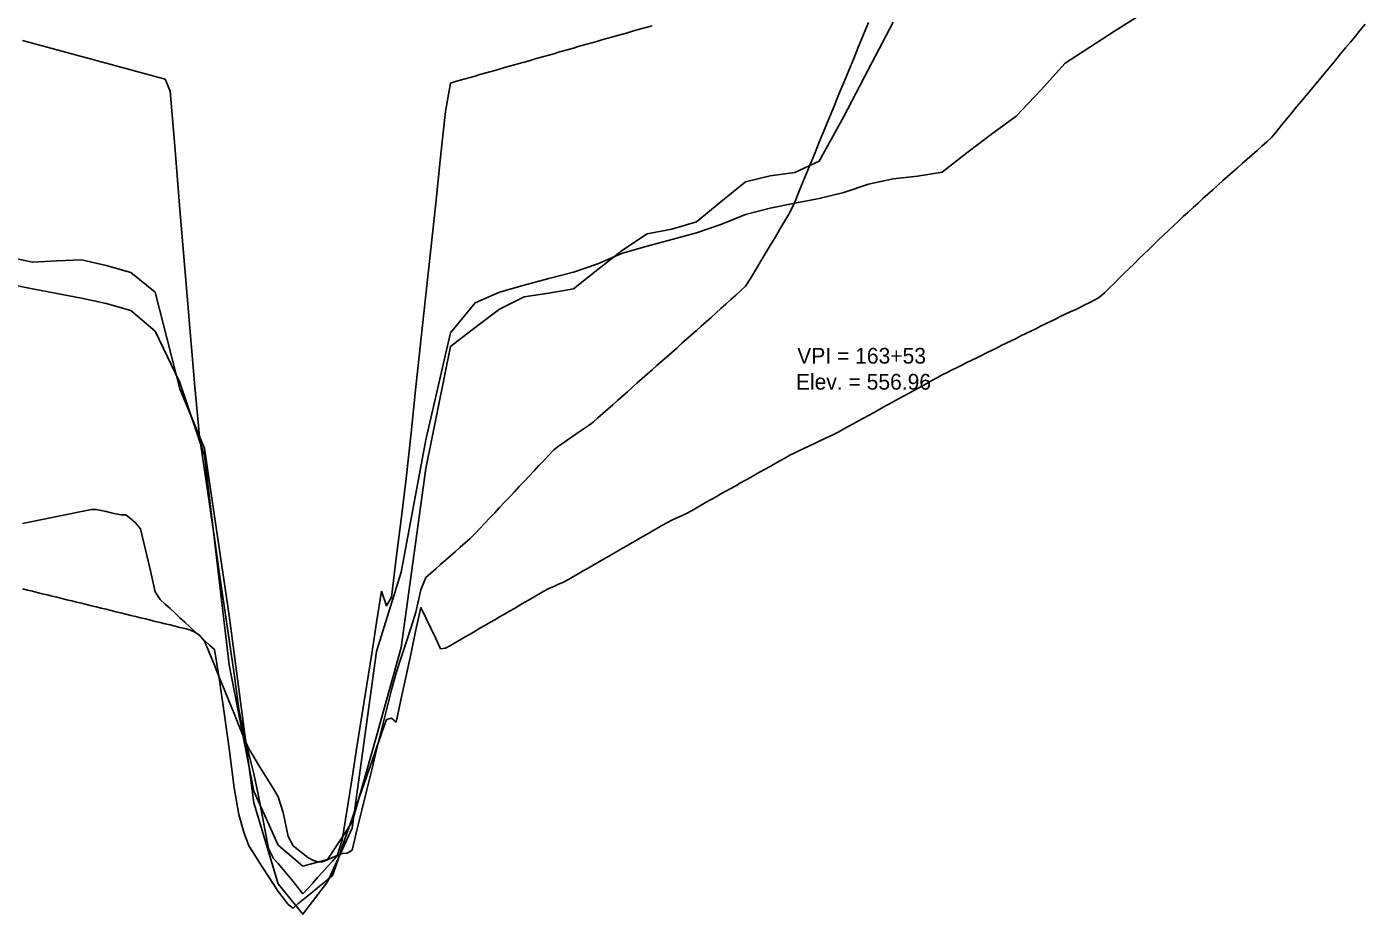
# Model space of a CAD drawing. Extents: x 1733571 to 1737171, y 1214895 to 1219895.
# Drawn here: x 1735360.8 to 1735633, y 1217773.2 to 1217953.6 of the extents above; entities that cross this region are included whole.
import ezdxf

# ---------------------------------------------------------------- set-up
doc = ezdxf.new("R2010")
doc.units = 0
for name, color, linetype in [('RD_DDB_Profile_EX', 7, 'Continuous'), ('RD_DDB_Profile_Lbl', 7, 'Continuous'), ('RD_Sketch1', 7, 'Continuous'), ('RD_Sketch2', 7, 'Continuous'), ('RD_Sketch3', 7, 'Continuous'), ('RD_Sketch4', 7, 'Continuous')]:
    doc.layers.add(name, color=color, linetype=linetype)

msp = doc.modelspace()

# ---------------------------------------------------------------- linework, layer by layer
at = {"layer": 'RD_DDB_Profile_EX'}
for points in [[(1735403.9887, 1217814.82595), (1735404.9887, 1217809.77976), (1735405.9887, 1217805.75508), (1735406.9887, 1217801.7304), (1735407.9887, 1217797.21719), (1735408.9887, 1217791.86495), (1735409.9887, 1217786.51271), (1735410.9887, 1217784.49053), (1735411.9887, 1217783.49618), (1735412.9887, 1217782.28653), (1735413.9887, 1217781.04718), (1735414.9887, 1217779.80783), (1735415.9887, 1217778.56847), (1735416.9887, 1217777.32912), (1735417.9887, 1217778.37844), (1735418.9887, 1217779.49479), (1735419.9887, 1217780.61114), (1735420.9887, 1217781.72749), (1735421.9887, 1217782.84384), (1735422.9887, 1217783.96019), (1735423.9887, 1217785.04162), (1735424.9887, 1217788.22009), (1735425.9887, 1217794.54679), (1735426.9887, 1217800.87348), (1735427.9887, 1217807.20017), (1735428.9887, 1217813.52686), (1735429.9887, 1217819.85355), (1735430.9887, 1217826.18025), (1735431.9887, 1217832.50694), (1735432.9887, 1217838.83898), (1735433.9887, 1217835.85161), (1735434.9887, 1217837.60997), (1735435.9887, 1217845.53436), (1735436.9887, 1217853.45875), (1735437.9887, 1217861.74643), (1735438.9887, 1217871.07993), (1735439.9887, 1217880.41343), (1735440.9887, 1217889.74693), (1735441.9887, 1217899.08043), (1735442.9887, 1217908.41393), (1735443.9887, 1217917.74743), (1735444.9887, 1217927.08094), (1735445.9887, 1217936.41444), (1735446.9887, 1217942.17422), (1735447.9887, 1217942.45977), (1735448.9887, 1217942.74531), (1735449.9887, 1217943.03086), (1735450.9887, 1217943.31641), (1735451.9887, 1217943.60195), (1735452.9887, 1217943.8868), (1735453.9887, 1217944.17071), (1735454.9887, 1217944.45463), (1735455.9887, 1217944.73854), (1735456.9887, 1217945.02246), (1735457.9887, 1217945.30637), (1735458.9887, 1217945.59029), (1735459.9887, 1217945.8742), (1735460.9887, 1217946.15812), (1735461.9887, 1217946.44203), (1735462.9887, 1217946.72595), (1735463.9887, 1217947.00986), (1735464.9887, 1217947.29378), (1735465.9887, 1217947.57769), (1735466.9887, 1217947.86161), (1735467.9887, 1217948.14552), (1735468.9887, 1217948.42944), (1735469.9887, 1217948.71335), (1735470.9887, 1217948.99727), (1735471.9887, 1217949.28817), (1735472.9887, 1217949.57685), (1735473.9887, 1217949.86134), (1735474.9887, 1217950.14583), (1735475.9887, 1217950.43032), (1735476.9887, 1217950.71481), (1735477.9887, 1217950.9993), (1735478.9887, 1217951.28379), (1735479.9887, 1217951.56828), (1735480.9887, 1217951.85278), (1735481.9887, 1217952.13727), (1735482.9887, 1217952.42176), (1735483.9887, 1217952.70625), (1735484.9887, 1217952.99074), (1735485.9887, 1217953.27523), (1735486.9887, 1217953.55972), (1735487.9887, 1217953.84421)], [(1735359.9887, 1217950.80532), (1735360.9887, 1217950.53363), (1735361.9887, 1217950.26194), (1735362.9887, 1217949.99025), (1735363.9887, 1217949.71856), (1735364.9887, 1217949.44687), (1735365.9887, 1217949.17518), (1735366.9887, 1217948.90787), (1735367.9887, 1217948.63642), (1735368.9887, 1217948.36496), (1735369.9887, 1217948.0935), (1735370.9887, 1217947.82205), (1735371.9887, 1217947.55059), (1735372.9887, 1217947.27913), (1735373.9887, 1217947.00768), (1735374.9887, 1217946.73622), (1735375.9887, 1217946.46476), (1735376.9887, 1217946.19331), (1735377.9887, 1217945.92185), (1735378.9887, 1217945.65039), (1735379.9887, 1217945.37894), (1735380.9887, 1217945.10748), (1735381.9887, 1217944.83603), (1735382.9887, 1217944.56457), (1735383.9887, 1217944.29311), (1735384.9887, 1217944.02166), (1735385.9887, 1217943.7502), (1735386.9887, 1217943.47874), (1735387.9887, 1217943.20729), (1735388.9887, 1217942.93583), (1735389.9887, 1217940.52821), (1735390.9887, 1217928.49516), (1735391.9887, 1217916.46924), (1735392.9887, 1217904.44768), (1735393.9887, 1217892.42613), (1735394.9887, 1217880.40457), (1735395.9887, 1217870.33538), (1735396.9887, 1217863.44004), (1735397.9887, 1217856.5447), (1735398.9887, 1217849.64936), (1735399.9887, 1217842.75402), (1735400.9887, 1217835.85868), (1735401.9887, 1217828.96334), (1735402.9887, 1217822.068), (1735403.9887, 1217814.82595)]]:
    msp.add_lwpolyline(points, dxfattribs=at)
at = {"layer": 'RD_Sketch1'}
for points in [[(1735505.9887, 1217899.95274), (1735506.9887, 1217900.85824), (1735507.9887, 1217902.43645), (1735508.9887, 1217904.10918), (1735509.9887, 1217905.78213), (1735510.9887, 1217907.45531), (1735511.9887, 1217909.12871), (1735512.9887, 1217910.80233), (1735513.9887, 1217912.47617), (1735514.9887, 1217914.15024), (1735515.9887, 1217915.82453), (1735516.9887, 1217917.95232), (1735517.9887, 1217920.39026), (1735518.9887, 1217922.82795), (1735519.9887, 1217925.26538), (1735520.9887, 1217927.70255), (1735521.9887, 1217930.13946), (1735522.9887, 1217932.57611), (1735523.9887, 1217935.0125), (1735524.9887, 1217937.44862), (1735525.9887, 1217939.88448), (1735526.9887, 1217942.32008), (1735527.9887, 1217944.75541), (1735528.9887, 1217947.19048), (1735529.9887, 1217949.62528), (1735530.9887, 1217952.05982), (1735531.9887, 1217954.49408)], [(1735405.9887, 1217806.7852), (1735406.9887, 1217805.16123), (1735407.9887, 1217803.53725), (1735408.9887, 1217801.91328), (1735409.9887, 1217800.28931), (1735410.9887, 1217798.66534), (1735411.9887, 1217797.04137), (1735412.9887, 1217793.84536), (1735413.9887, 1217788.94765), (1735414.9887, 1217787.08806), (1735415.9887, 1217786.2937), (1735416.9887, 1217785.49933), (1735417.9887, 1217784.70497), (1735418.9887, 1217784.13339), (1735419.9887, 1217783.84017), (1735420.9887, 1217783.79345), (1735421.9887, 1217784.22864), (1735422.9887, 1217784.66384), (1735423.9887, 1217785.09904), (1735424.9887, 1217785.53424), (1735425.9887, 1217785.57916), (1735426.9887, 1217786.21749), (1735427.9887, 1217790.28585), (1735428.9887, 1217794.35422), (1735429.9887, 1217798.42258), (1735430.9887, 1217802.49095), (1735431.9887, 1217806.55932), (1735432.9887, 1217810.62768), (1735433.9887, 1217814.69605), (1735434.9887, 1217818.76442), (1735435.9887, 1217822.27353), (1735436.9887, 1217825.35337), (1735437.9887, 1217828.43321), (1735438.9887, 1217831.51305), (1735439.9887, 1217834.6022), (1735440.9887, 1217839.15742), (1735441.9887, 1217841.66362), (1735442.9887, 1217842.54373), (1735443.9887, 1217843.42385), (1735444.9887, 1217844.30396), (1735445.9887, 1217845.18408), (1735446.9887, 1217846.06419), (1735447.9887, 1217846.94431), (1735448.9887, 1217847.82443), (1735449.9887, 1217848.70454), (1735450.9887, 1217849.58466), (1735451.9887, 1217850.55494), (1735452.9887, 1217851.61814), (1735453.9887, 1217852.68134), (1735454.9887, 1217853.74454), (1735455.9887, 1217854.80774), (1735456.9887, 1217855.87094), (1735457.9887, 1217856.93415), (1735458.9887, 1217857.99735), (1735459.9887, 1217859.06055), (1735460.9887, 1217860.12375), (1735461.9887, 1217861.18695), (1735462.9887, 1217862.25015), (1735463.9887, 1217863.31335), (1735464.9887, 1217864.37655), (1735465.9887, 1217865.43976), (1735466.9887, 1217866.50296), (1735467.9887, 1217867.56616), (1735468.9887, 1217868.35172), (1735469.9887, 1217869.04359), (1735470.9887, 1217869.73546), (1735471.9887, 1217870.42733), (1735472.9887, 1217871.1192), (1735473.9887, 1217871.81107), (1735474.9887, 1217872.50294), (1735475.9887, 1217873.20844), (1735476.9887, 1217874.09588), (1735477.9887, 1217874.98332), (1735478.9887, 1217875.87077), (1735479.9887, 1217876.75821), (1735480.9887, 1217877.64566), (1735481.9887, 1217878.5331), (1735482.9887, 1217879.42055), (1735483.9887, 1217880.30799), (1735484.9887, 1217881.19543), (1735485.9887, 1217882.08288), (1735486.9887, 1217882.97032), (1735487.9887, 1217883.85777), (1735488.9887, 1217884.74521), (1735489.9887, 1217885.63266), (1735490.9887, 1217886.5201), (1735491.9887, 1217887.40754), (1735492.9887, 1217888.29499), (1735493.9887, 1217889.18243), (1735494.9887, 1217890.06988), (1735495.9887, 1217890.95732), (1735496.9887, 1217891.84477), (1735497.9887, 1217892.73221), (1735498.9887, 1217893.62677), (1735499.9887, 1217894.52914), (1735500.9887, 1217895.43196), (1735501.9887, 1217896.33523), (1735502.9887, 1217897.23894), (1735503.9887, 1217898.14309), (1735504.9887, 1217899.0477), (1735505.9887, 1217899.95274)], [(1735359.9887, 1217839.32341), (1735360.9887, 1217839.07863), (1735361.9887, 1217838.83385), (1735362.9887, 1217838.58908), (1735363.9887, 1217838.3443), (1735364.9887, 1217838.09952), (1735365.9887, 1217837.85474), (1735366.9887, 1217837.60996), (1735367.9887, 1217837.36518), (1735368.9887, 1217837.1204), (1735369.9887, 1217836.87562), (1735370.9887, 1217836.63084), (1735371.9887, 1217836.38607), (1735372.9887, 1217836.14129), (1735373.9887, 1217835.89651), (1735374.9887, 1217835.65173), (1735375.9887, 1217835.40695), (1735376.9887, 1217835.16217), (1735377.9887, 1217834.91739), (1735378.9887, 1217834.67261), (1735379.9887, 1217834.42783), (1735380.9887, 1217834.18306), (1735381.9887, 1217833.93828), (1735382.9887, 1217833.6935), (1735383.9887, 1217833.44872), (1735384.9887, 1217833.20394), (1735385.9887, 1217832.95916), (1735386.9887, 1217832.71438), (1735387.9887, 1217832.4696), (1735388.9887, 1217832.22483), (1735389.9887, 1217831.98005), (1735390.9887, 1217831.73527), (1735391.9887, 1217831.49049), (1735392.9887, 1217831.24571), (1735393.9887, 1217831.00093), (1735394.9887, 1217830.5065), (1735395.9887, 1217829.92733), (1735396.9887, 1217828.71859), (1735397.9887, 1217826.26478), (1735398.9887, 1217823.81096), (1735399.9887, 1217821.35715), (1735400.9887, 1217818.90334), (1735401.9887, 1217816.44952), (1735402.9887, 1217813.99571), (1735403.9887, 1217811.5419), (1735404.9887, 1217809.08808), (1735405.9887, 1217806.7852)]]:
    msp.add_lwpolyline(points, dxfattribs=at)
at = {"layer": 'RD_Sketch2'}
for points in [[(1735599.9887, 1217918.67154), (1735600.9887, 1217919.57654), (1735601.9887, 1217920.47898), (1735602.9887, 1217921.37884), (1735603.9887, 1217922.27614), (1735604.9887, 1217923.17086), (1735605.9887, 1217924.06302), (1735606.9887, 1217924.9526), (1735607.9887, 1217925.83961), (1735608.9887, 1217926.72405), (1735609.9887, 1217927.60592), (1735610.9887, 1217928.48522), (1735611.9887, 1217929.36195), (1735612.9887, 1217930.2361), (1735613.9887, 1217931.13858), (1735614.9887, 1217932.37074), (1735615.9887, 1217933.60246), (1735616.9887, 1217934.83374), (1735617.9887, 1217936.06458), (1735618.9887, 1217937.3458), (1735619.9887, 1217938.40706), (1735620.9887, 1217939.63344), (1735621.9887, 1217940.84505), (1735622.9887, 1217942.05611), (1735623.9887, 1217943.26664), (1735624.9887, 1217944.47662), (1735625.9887, 1217945.68607), (1735626.9887, 1217946.89498), (1735627.9887, 1217948.10334), (1735628.9887, 1217949.31117), (1735629.9887, 1217950.51845), (1735630.9887, 1217951.72519), (1735631.9887, 1217952.93139), (1735632.9887, 1217954.13704)], [(1735499.9887, 1217857.49408), (1735500.9887, 1217858.05644), (1735501.9887, 1217858.61871), (1735502.9887, 1217859.1809), (1735503.9887, 1217859.74301), (1735504.9887, 1217860.30503), (1735505.9887, 1217860.86698), (1735506.9887, 1217861.42883), (1735507.9887, 1217861.99061), (1735508.9887, 1217862.5523), (1735509.9887, 1217863.11391), (1735510.9887, 1217863.67543), (1735511.9887, 1217864.23687), (1735512.9887, 1217864.79823), (1735513.9887, 1217865.3595), (1735514.9887, 1217865.92068), (1735515.9887, 1217866.48179), (1735516.9887, 1217867.01446), (1735517.9887, 1217867.47988), (1735518.9887, 1217867.94516), (1735519.9887, 1217868.4103), (1735520.9887, 1217868.88407), (1735521.9887, 1217869.36444), (1735522.9887, 1217869.84466), (1735523.9887, 1217870.32474), (1735524.9887, 1217870.80467), (1735525.9887, 1217871.28661), (1735526.9887, 1217871.83819), (1735527.9887, 1217872.38954), (1735528.9887, 1217872.94067), (1735529.9887, 1217873.49157), (1735530.9887, 1217874.04225), (1735531.9887, 1217874.5927), (1735532.9887, 1217875.14293), (1735533.9887, 1217875.69293), (1735534.9887, 1217876.2427), (1735535.9887, 1217876.79225), (1735536.9887, 1217877.34157), (1735537.9887, 1217877.89067), (1735538.9887, 1217878.43954), (1735539.9887, 1217878.98818), (1735540.9887, 1217879.5366), (1735541.9887, 1217880.08479), (1735542.9887, 1217880.63275), (1735543.9887, 1217881.18049), (1735544.9887, 1217881.728), (1735545.9887, 1217882.27528), (1735546.9887, 1217882.82233), (1735547.9887, 1217883.33554), (1735548.9887, 1217883.83165), (1735549.9887, 1217884.32753), (1735550.9887, 1217884.82318), (1735551.9887, 1217885.3186), (1735552.9887, 1217885.81379), (1735553.9887, 1217886.30875), (1735554.9887, 1217886.80348), (1735555.9887, 1217887.29798), (1735556.9887, 1217887.79225), (1735557.9887, 1217888.28629), (1735558.9887, 1217888.78009), (1735559.9887, 1217889.27367), (1735560.9887, 1217889.76702), (1735561.9887, 1217890.26013), (1735562.9887, 1217890.75301), (1735563.9887, 1217891.24566), (1735564.9887, 1217891.73808), (1735565.9887, 1217892.23027), (1735566.9887, 1217892.72222), (1735567.9887, 1217893.21394), (1735568.9887, 1217893.70543), (1735569.9887, 1217894.19669), (1735570.9887, 1217894.69049), (1735571.9887, 1217895.19796), (1735572.9887, 1217895.66946), (1735573.9887, 1217896.07678), (1735574.9887, 1217896.55105), (1735575.9887, 1217897.06494), (1735576.9887, 1217897.57849), (1735577.9887, 1217898.0917), (1735578.9887, 1217898.60457), (1735579.9887, 1217899.53784), (1735580.9887, 1217900.52859), (1735581.9887, 1217901.51677), (1735582.9887, 1217902.5024), (1735583.9887, 1217903.48546), (1735584.9887, 1217904.46596), (1735585.9887, 1217905.4439), (1735586.9887, 1217906.41927), (1735587.9887, 1217907.39208), (1735588.9887, 1217908.36233), (1735589.9887, 1217909.33001), (1735590.9887, 1217910.29513), (1735591.9887, 1217911.25769), (1735592.9887, 1217912.21767), (1735593.9887, 1217913.1751), (1735594.9887, 1217914.10799), (1735595.9887, 1217915.02583), (1735596.9887, 1217915.94111), (1735597.9887, 1217916.85382), (1735598.9887, 1217917.76397), (1735599.9887, 1217918.67154)], [(1735399.9887, 1217821.15801), (1735400.9887, 1217814.12766), (1735401.9887, 1217806.88952), (1735402.9887, 1217798.85198), (1735403.9887, 1217793.44089), (1735404.9887, 1217789.8233), (1735405.9887, 1217787.0528), (1735406.9887, 1217785.49577), (1735407.9887, 1217783.93874), (1735408.9887, 1217782.38171), (1735409.9887, 1217780.82468), (1735410.9887, 1217779.26765), (1735411.9887, 1217777.78403), (1735412.9887, 1217776.47306), (1735413.9887, 1217775.16209), (1735414.9887, 1217774.41884), (1735415.9887, 1217775.2426), (1735416.9887, 1217776.06637), (1735417.9887, 1217776.89014), (1735418.9887, 1217777.71391), (1735419.9887, 1217778.53768), (1735420.9887, 1217779.36144), (1735421.9887, 1217780.18521), (1735422.9887, 1217781.00898), (1735423.9887, 1217783.703), (1735424.9887, 1217786.86902), (1735425.9887, 1217789.74918), (1735426.9887, 1217792.62935), (1735427.9887, 1217795.50951), (1735428.9887, 1217798.38968), (1735429.9887, 1217801.26984), (1735430.9887, 1217804.15), (1735431.9887, 1217807.03017), (1735432.9887, 1217809.91033), (1735433.9887, 1217812.79049), (1735434.9887, 1217813.01062), (1735435.9887, 1217812.22575), (1735436.9887, 1217817.0195), (1735437.9887, 1217821.66771), (1735438.9887, 1217826.31591), (1735439.9887, 1217830.96411), (1735440.9887, 1217835.50356), (1735441.9887, 1217833.40225), (1735442.9887, 1217831.30094), (1735443.9887, 1217829.19962), (1735444.9887, 1217827.09831), (1735445.9887, 1217827.23971), (1735446.9887, 1217827.81955), (1735447.9887, 1217828.39938), (1735448.9887, 1217828.97922), (1735449.9887, 1217829.55906), (1735450.9887, 1217830.1389), (1735451.9887, 1217830.71873), (1735452.9887, 1217831.29857), (1735453.9887, 1217831.87841), (1735454.9887, 1217832.45824), (1735455.9887, 1217833.03808), (1735456.9887, 1217833.61792), (1735457.9887, 1217834.19776), (1735458.9887, 1217834.77759), (1735459.9887, 1217835.35743), (1735460.9887, 1217835.93727), (1735461.9887, 1217836.5171), (1735462.9887, 1217837.09694), (1735463.9887, 1217837.67678), (1735464.9887, 1217838.25662), (1735465.9887, 1217838.83645), (1735466.9887, 1217839.36569), (1735467.9887, 1217839.80736), (1735468.9887, 1217840.24903), (1735469.9887, 1217840.6907), (1735470.9887, 1217841.24759), (1735471.9887, 1217841.82263), (1735472.9887, 1217842.39766), (1735473.9887, 1217842.9727), (1735474.9887, 1217843.54773), (1735475.9887, 1217844.12277), (1735476.9887, 1217844.6978), (1735477.9887, 1217845.27284), (1735478.9887, 1217845.84787), (1735479.9887, 1217846.42291), (1735480.9887, 1217846.99794), (1735481.9887, 1217847.57298), (1735482.9887, 1217848.14801), (1735483.9887, 1217848.72305), (1735484.9887, 1217849.29808), (1735485.9887, 1217849.87312), (1735486.9887, 1217850.44815), (1735487.9887, 1217851.02319), (1735488.9887, 1217851.59822), (1735489.9887, 1217852.17326), (1735490.9887, 1217852.74829), (1735491.9887, 1217853.27419), (1735492.9887, 1217853.73592), (1735493.9887, 1217854.19765), (1735494.9887, 1217854.65938), (1735495.9887, 1217855.22065), (1735496.9887, 1217855.7925), (1735497.9887, 1217856.36435), (1735498.9887, 1217856.93165), (1735499.9887, 1217857.49408)], [(1735359.9887, 1217852.59901), (1735360.9887, 1217852.80184), (1735361.9887, 1217853.00467), (1735362.9887, 1217853.2075), (1735363.9887, 1217853.41033), (1735364.9887, 1217853.61315), (1735365.9887, 1217853.81598), (1735366.9887, 1217854.01881), (1735367.9887, 1217854.22164), (1735368.9887, 1217854.42447), (1735369.9887, 1217854.6273), (1735370.9887, 1217854.83013), (1735371.9887, 1217855.03296), (1735372.9887, 1217855.23579), (1735373.9887, 1217855.43862), (1735374.9887, 1217855.49378), (1735375.9887, 1217855.26783), (1735376.9887, 1217855.04188), (1735377.9887, 1217854.81592), (1735378.9887, 1217854.58997), (1735379.9887, 1217854.36546), (1735380.9887, 1217854.37244), (1735381.9887, 1217853.57197), (1735382.9887, 1217852.7715), (1735383.9887, 1217851.53828), (1735384.9887, 1217847.26929), (1735385.9887, 1217843.00029), (1735386.9887, 1217838.73129), (1735387.9887, 1217837.16792), (1735388.9887, 1217836.24093), (1735389.9887, 1217835.31394), (1735390.9887, 1217834.38695), (1735391.9887, 1217833.45995), (1735392.9887, 1217832.53296), (1735393.9887, 1217831.60597), (1735394.9887, 1217830.67898), (1735395.9887, 1217829.75199), (1735396.9887, 1217828.825), (1735397.9887, 1217827.89801), (1735398.9887, 1217826.97102), (1735399.9887, 1217821.15801)]]:
    msp.add_lwpolyline(points, dxfattribs=at)
at = {"layer": 'RD_Sketch3'}
for points in [[(1735401.9887, 1217823.86729), (1735406.9887, 1217798.21412), (1735411.9887, 1217787.18875), (1735416.9887, 1217782.96352), (1735421.9887, 1217784.28082), (1735426.9887, 1217791.88528), (1735431.9887, 1217809.35829), (1735436.9887, 1217827.40234), (1735441.9887, 1217863.78096), (1735446.9887, 1217888.62718), (1735451.9887, 1217892.47267), (1735456.9887, 1217896.22365), (1735461.9887, 1217898.73016), (1735466.9887, 1217899.44107), (1735471.9887, 1217900.35474), (1735476.9887, 1217904.27007), (1735481.9887, 1217908.18539), (1735486.9887, 1217911.5303), (1735491.9887, 1217912.47714), (1735496.9887, 1217913.9407), (1735501.9887, 1217918.05651), (1735506.9887, 1217922.06222), (1735511.9887, 1217923.28013), (1735516.9887, 1217923.96428), (1735521.9887, 1217926.26168), (1735526.9887, 1217935.4014), (1735531.9887, 1217944.98611), (1735536.9887, 1217954.56098)], [(1735356.9887, 1217901.34097), (1735361.9887, 1217900.36213), (1735366.9887, 1217899.3833), (1735371.9887, 1217898.40446), (1735376.9887, 1217897.34685), (1735381.9887, 1217895.95356), (1735386.9887, 1217891.6957), (1735391.9887, 1217881.28992), (1735396.9887, 1217866.45176), (1735401.9887, 1217823.86729)]]:
    msp.add_lwpolyline(points, dxfattribs=at)
at = {"layer": 'RD_Sketch4'}
for points in [[(1735401.9887, 1217833.9301), (1735406.9887, 1217795.78147), (1735411.9887, 1217779.33957), (1735416.9887, 1217773.15958), (1735421.9887, 1217779.74556), (1735426.9887, 1217790.67107), (1735431.9887, 1217826.57867), (1735436.9887, 1217842.72417), (1735441.9887, 1217869.60791), (1735446.9887, 1217891.39753), (1735451.9887, 1217897.51196), (1735456.9887, 1217899.64651), (1735461.9887, 1217901.06811), (1735466.9887, 1217902.39937), (1735471.9887, 1217903.73064), (1735476.9887, 1217905.41047), (1735481.9887, 1217907.5773), (1735486.9887, 1217909.04162), (1735491.9887, 1217910.37481), (1735496.9887, 1217911.70799), (1735501.9887, 1217913.38584), (1735506.9887, 1217915.44714), (1735511.9887, 1217916.76216), (1735516.9887, 1217917.78396), (1735521.9887, 1217918.71224), (1735526.9887, 1217919.94532), (1735531.9887, 1217921.59146), (1735536.9887, 1217922.67203), (1735541.9887, 1217923.2756), (1735546.9887, 1217924.07509), (1735551.9887, 1217927.95831), (1735556.9887, 1217931.75325), (1735561.9887, 1217935.45988), (1735566.9887, 1217940.67391), (1735571.9887, 1217946.1939), (1735576.9887, 1217949.48358), (1735581.9887, 1217952.69925), (1735586.9887, 1217955.84089)], [(1735356.9887, 1217906.86968), (1735361.9887, 1217905.75176), (1735366.9887, 1217906.03319), (1735371.9887, 1217906.19939), (1735376.9887, 1217905.06962), (1735381.9887, 1217903.63882), (1735386.9887, 1217899.63645), (1735391.9887, 1217879.97329), (1735396.9887, 1217867.85991), (1735401.9887, 1217833.9301)]]:
    msp.add_lwpolyline(points, dxfattribs=at)

# ---------------------------------------------------------------- texts
at = {"layer": 'RD_DDB_Profile_Lbl'}
for s, p in [('VPI = 163+53', (1735517.50413, 1217885.12394)), ('Elev. = 556.96', (1735517.23343, 1217879.83269))]:
    msp.add_text(s, height=3.2, dxfattribs=at).set_placement(p)

doc.saveas('drawing.dxf')
